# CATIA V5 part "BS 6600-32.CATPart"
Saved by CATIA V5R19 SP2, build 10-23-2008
Part number: BS 6600-32
Bounding box of the stored display mesh (mm): x -59.975 to 59.975, y -59.975 to 59.975, z 0 to 139
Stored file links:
  C:\Users\Bora\Desktop\3D Katı model\BS serisi\BS 6600\BS 6600-32.CATPart
  C:\Program Files\Dassault Systemes\B19\intel_a\reffiles\standard\MetricThickPitch.txt
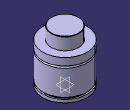
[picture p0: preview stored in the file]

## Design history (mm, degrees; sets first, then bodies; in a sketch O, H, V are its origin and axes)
Body1 (main body)
  Sketch1 on yz-plane, origin (0, 0, 0), H (0, 1, 0), V (0, 0, 1)
    point P1 (60, 86)
    point P2 (60, 81)
    point P3 (60, 86)
    point P7 (37.5, 138)
    point P9 (37.5, 138)
    point P14 (60, 81)
    arc A1 centre (60, 83.5) radius 2.5 from (60, 86) to (60, 81) ccw
    line L1 (60, 86) -> (60, 106)
    line L2 (60, 0) -> (60, 8)
    arc A2 centre (36.5, 138) radius 1 from (37.5, 138) to (36.5, 139) ccw
    line L3 (37.5, 138) -> (37.5, 106)
    line L4 (56, 13) -> (56, 8)
    line L5 (60, 13) -> (60, 81)
    line L6 (36.5, 139) -> (0, 139)
    point P15 (0, 139)
    line L7 (37.5, 106) -> (60, 106)
    line L8 (56, 13) -> (60, 13)
    line L9 (56, 8) -> (60, 8)
    line L10 (60, 0) -> (0, 0)
    coincidence: P15 V, P1 P3, P2 P14, P7 P9
    tangency: L6 A2
    horizontal: L7 H, L8 H, L9 H, L10 H
  Shaft1: profile Sketch1, axis Sketch1.V, angle 360
  Sketch2 on face of Shaft1 from Sketch1.L10, origin (0, 0, 0), H (1, 0, 0), V (0, -1, 0)
    point P1 (40, 0)
    distance P1 V = 40
  Hole1: placed by Sketch2, at (40, 0, 0) direction (0, 0, 1), diameter 8.376, depth 8, threaded "M10", thread diameter 10, thread depth 8, pitch 1.5
  CircPattern1: of Hole1, instances 4, angular step 90, axis from xy-plane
